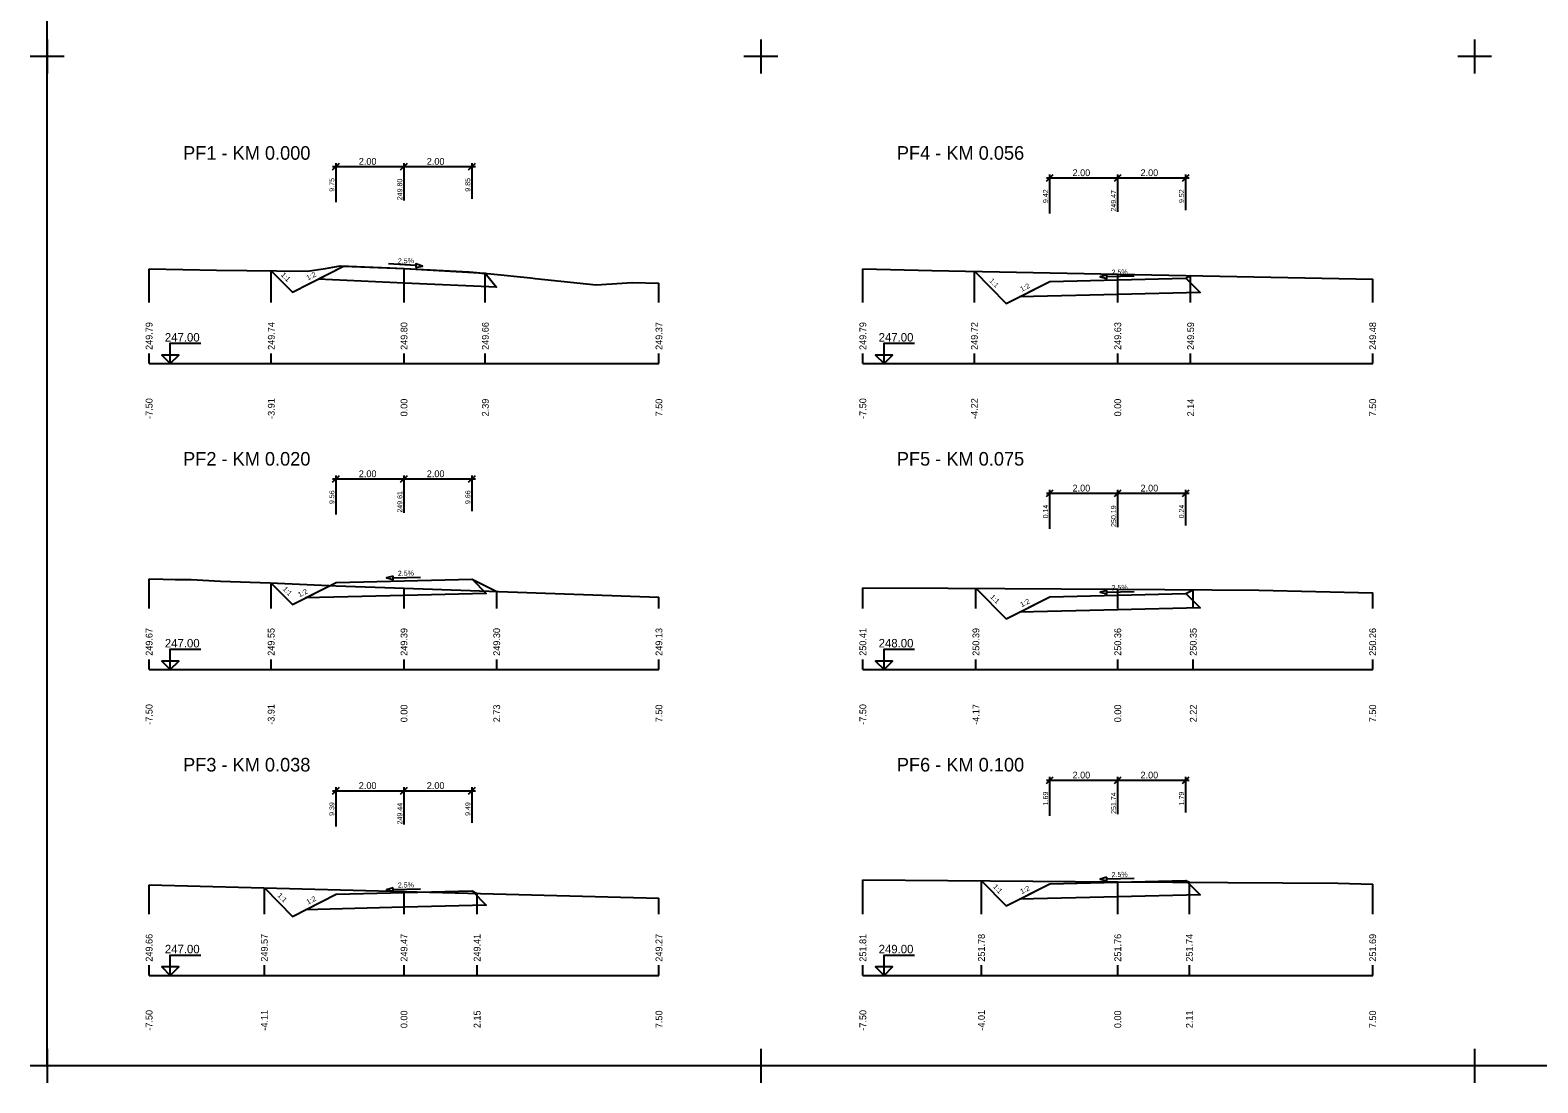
# Model space of a CAD drawing. Extents: x -5 to 1895, y -2 to 602.
# Drawn here: x -5 to 438.6, y -1.6 to 308.1 of the extents above; entities that cross this region are included whole.
import ezdxf

# ---------------------------------------------------------------- set-up
doc = ezdxf.new("R2010")
doc.units = 0
for name, color, linetype in [('KOTA', 7, 'Continuous'), ('KOTA_DELKY', 7, 'Continuous'), ('KOTA_DELKY_CONT', 7, 'Continuous'), ('NS_TELESO_VOZOVKY', 7, 'Continuous'), ('NS_V_PF', 7, 'Continuous'), ('REZY_PF_PUVODNI', 7, 'Continuous'), ('SESTAVY_REZU_PF', 7, 'Continuous'), ('SKLON', 7, 'Continuous'), ('SVK', 7, 'Continuous')]:
    doc.layers.add(name, color=color, linetype=linetype)

msp = doc.modelspace()

# ---------------------------------------------------------------- linework, layer by layer
for p, q in [((0, 305.39), (0, 295.39)), ((0, 305.39), (0, 295.39)), ((0, 305.39), (0, 295.39)), ((0, 305.39), (0, 295.39)), ((0, 305.39), (0, 295.39)), ((0, 305.39), (0, 295.39)), ((0, 305.39), (0, 295.39)), ((0, 305.39), (0, 295.39)), ((0, 305.39), (0, 295.39)), ((0, 305.39), (0, 295.39)), ((210, 305.39), (210, 295.39)), ((210, 305.39), (210, 295.39)), ((210, 305.39), (210, 295.39)), ((210, 305.39), (210, 295.39)), ((210, 305.39), (210, 295.39)), ((210, 305.39), (210, 295.39)), ((210, 305.39), (210, 295.39)), ((210, 305.39), (210, 295.39)), ((210, 305.39), (210, 295.39)), ((210, 305.39), (210, 295.39)), ((210, 305.39), (210, 295.39)), ((210, 305.39), (210, 295.39)), ((210, 305.39), (210, 295.39)), ((210, 305.39), (210, 295.39)), ((210, 305.39), (210, 295.39)), ((210, 305.39), (210, 295.39)), ((210, 305.39), (210, 295.39)), ((210, 305.39), (210, 295.39)), ((210, 305.39), (210, 295.39)), ((210, 305.39), (210, 295.39)), ((210, 305.39), (210, 295.39)), ((210, 305.39), (210, 295.39)), ((210, 305.39), (210, 295.39)), ((210, 305.39), (210, 295.39)), ((210, 305.39), (210, 295.39)), ((210, 305.39), (210, 295.39)), ((210, 305.39), (210, 295.39)), ((210, 305.39), (210, 295.39)), ((210, 305.39), (210, 295.39)), ((210, 305.39), (210, 295.39)), ((420, 305.39), (420, 295.39)), ((420, 305.39), (420, 295.39)), ((420, 305.39), (420, 295.39)), ((420, 305.39), (420, 295.39)), ((420, 305.39), (420, 295.39)), ((420, 305.39), (420, 295.39)), ((420, 305.39), (420, 295.39)), ((420, 305.39), (420, 295.39)), ((420, 305.39), (420, 295.39)), ((420, 305.39), (420, 295.39)), ((420, 305.39), (420, 295.39)), ((420, 305.39), (420, 295.39)), ((420, 305.39), (420, 295.39)), ((420, 305.39), (420, 295.39)), ((420, 305.39), (420, 295.39)), ((420, 305.39), (420, 295.39)), ((420, 305.39), (420, 295.39)), ((420, 305.39), (420, 295.39)), ((420, 305.39), (420, 295.39)), ((420, 305.39), (420, 295.39)), ((420, 305.39), (420, 295.39)), ((420, 305.39), (420, 295.39)), ((420, 305.39), (420, 295.39)), ((420, 305.39), (420, 295.39)), ((420, 305.39), (420, 295.39)), ((420, 305.39), (420, 295.39)), ((420, 305.39), (420, 295.39)), ((420, 305.39), (420, 295.39)), ((420, 305.39), (420, 295.39)), ((420, 305.39), (420, 295.39)), ((5, 300.39), (-5, 300.39)), ((5, 300.39), (-5, 300.39)), ((5, 300.39), (-5, 300.39)), ((5, 300.39), (-5, 300.39)), ((5, 300.39), (-5, 300.39)), ((5, 300.39), (-5, 300.39)), ((5, 300.39), (-5, 300.39)), ((5, 300.39), (-5, 300.39)), ((5, 300.39), (-5, 300.39)), ((5, 300.39), (-5, 300.39)), ((215, 300.39), (205, 300.39)), ((215, 300.39), (205, 300.39)), ((215, 300.39), (205, 300.39)), ((215, 300.39), (205, 300.39)), ((215, 300.39), (205, 300.39)), ((215, 300.39), (205, 300.39)), ((215, 300.39), (205, 300.39)), ((215, 300.39), (205, 300.39)), ((215, 300.39), (205, 300.39)), ((215, 300.39), (205, 300.39)), ((215, 300.39), (205, 300.39)), ((215, 300.39), (205, 300.39)), ((215, 300.39), (205, 300.39)), ((215, 300.39), (205, 300.39)), ((215, 300.39), (205, 300.39)), ((215, 300.39), (205, 300.39)), ((215, 300.39), (205, 300.39)), ((215, 300.39), (205, 300.39)), ((215, 300.39), (205, 300.39)), ((215, 300.39), (205, 300.39)), ((215, 300.39), (205, 300.39)), ((215, 300.39), (205, 300.39)), ((215, 300.39), (205, 300.39)), ((215, 300.39), (205, 300.39)), ((215, 300.39), (205, 300.39)), ((215, 300.39), (205, 300.39)), ((215, 300.39), (205, 300.39)), ((215, 300.39), (205, 300.39)), ((215, 300.39), (205, 300.39)), ((215, 300.39), (205, 300.39)), ((425, 300.39), (415, 300.39)), ((425, 300.39), (415, 300.39)), ((425, 300.39), (415, 300.39)), ((425, 300.39), (415, 300.39)), ((425, 300.39), (415, 300.39)), ((425, 300.39), (415, 300.39)), ((425, 300.39), (415, 300.39)), ((425, 300.39), (415, 300.39)), ((425, 300.39), (415, 300.39)), ((425, 300.39), (415, 300.39)), ((425, 300.39), (415, 300.39)), ((425, 300.39), (415, 300.39)), ((425, 300.39), (415, 300.39)), ((425, 300.39), (415, 300.39)), ((425, 300.39), (415, 300.39)), ((425, 300.39), (415, 300.39)), ((425, 300.39), (415, 300.39)), ((425, 300.39), (415, 300.39)), ((425, 300.39), (415, 300.39)), ((425, 300.39), (415, 300.39)), ((425, 300.39), (415, 300.39)), ((425, 300.39), (415, 300.39)), ((425, 300.39), (415, 300.39)), ((425, 300.39), (415, 300.39)), ((425, 300.39), (415, 300.39)), ((425, 300.39), (415, 300.39)), ((425, 300.39), (415, 300.39)), ((425, 300.39), (415, 300.39)), ((425, 300.39), (415, 300.39)), ((425, 300.39), (415, 300.39)), ((0, 8.39), (0, -1.61)), ((0, 8.39), (0, -1.61)), ((0, 8.39), (0, -1.61)), ((0, 8.39), (0, -1.61)), ((210, 8.39), (210, -1.61)), ((210, 8.39), (210, -1.61)), ((210, 8.39), (210, -1.61)), ((210, 8.39), (210, -1.61)), ((210, 8.39), (210, -1.61)), ((210, 8.39), (210, -1.61)), ((210, 8.39), (210, -1.61)), ((210, 8.39), (210, -1.61)), ((210, 8.39), (210, -1.61)), ((210, 8.39), (210, -1.61)), ((210, 8.39), (210, -1.61)), ((210, 8.39), (210, -1.61)), ((420, 8.39), (420, -1.61)), ((420, 8.39), (420, -1.61)), ((420, 8.39), (420, -1.61)), ((420, 8.39), (420, -1.61)), ((420, 8.39), (420, -1.61)), ((420, 8.39), (420, -1.61)), ((420, 8.39), (420, -1.61)), ((420, 8.39), (420, -1.61)), ((420, 8.39), (420, -1.61)), ((420, 8.39), (420, -1.61)), ((420, 8.39), (420, -1.61)), ((420, 8.39), (420, -1.61)), ((5, 3.39), (-5, 3.39)), ((5, 3.39), (-5, 3.39)), ((5, 3.39), (-5, 3.39)), ((5, 3.39), (-5, 3.39)), ((215, 3.39), (205, 3.39)), ((215, 3.39), (205, 3.39)), ((215, 3.39), (205, 3.39)), ((215, 3.39), (205, 3.39)), ((215, 3.39), (205, 3.39)), ((215, 3.39), (205, 3.39)), ((215, 3.39), (205, 3.39)), ((215, 3.39), (205, 3.39)), ((215, 3.39), (205, 3.39)), ((215, 3.39), (205, 3.39)), ((215, 3.39), (205, 3.39)), ((215, 3.39), (205, 3.39)), ((425, 3.39), (415, 3.39)), ((425, 3.39), (415, 3.39)), ((425, 3.39), (415, 3.39)), ((425, 3.39), (415, 3.39)), ((425, 3.39), (415, 3.39)), ((425, 3.39), (415, 3.39)), ((425, 3.39), (415, 3.39)), ((425, 3.39), (415, 3.39)), ((425, 3.39), (415, 3.39)), ((425, 3.39), (415, 3.39)), ((425, 3.39), (415, 3.39)), ((425, 3.39), (415, 3.39))]:
    msp.add_line(p, q)
msp.add_lwpolyline([(0, 597.39), (1890, 597.39), (1890, 3.39), (0, 3.39)], close=True)
at = {"layer": 'KOTA'}
for points in [[(36.22, 212.5), (33.72, 212.5), (36.22, 210), (36.22, 216), (45.22, 216)], [(246.22, 212.5), (243.72, 212.5), (246.22, 210), (246.22, 216), (255.22, 216)], [(36.22, 210), (38.72, 212.5), (36.22, 212.5)], [(246.22, 210), (248.72, 212.5), (246.22, 212.5)], [(36.22, 122.5), (33.72, 122.5), (36.22, 120), (36.22, 126), (45.22, 126)], [(246.22, 122.5), (243.72, 122.5), (246.22, 120), (246.22, 126), (255.22, 126)], [(36.22, 120), (38.72, 122.5), (36.22, 122.5)], [(246.22, 120), (248.72, 122.5), (246.22, 122.5)], [(36.22, 32.5), (33.72, 32.5), (36.22, 30), (36.22, 36), (45.22, 36)], [(246.22, 32.5), (243.72, 32.5), (246.22, 30), (246.22, 36), (255.22, 36)], [(36.22, 30), (38.72, 32.5), (36.22, 32.5)], [(246.22, 30), (248.72, 32.5), (246.22, 32.5)]]:
    msp.add_lwpolyline(points, dxfattribs=at)
at = {"layer": 'KOTA_DELKY'}
for points in [[(84, 267.01), (86, 269.01)], [(84, 268.01), (106, 268.01)], [(85, 257.51), (85, 269.01)], [(104, 267.01), (106, 269.01)], [(104, 267.01), (106, 269.01)], [(104, 268.01), (126, 268.01)], [(105, 258.01), (105, 269.01)], [(105, 258.01), (105, 269.01)], [(124, 267.01), (126, 269.01)], [(125, 258.51), (125, 269.01)], [(294, 263.68), (296, 265.68)], [(294, 264.68), (316, 264.68)], [(295, 254.18), (295, 265.68)], [(314, 263.68), (316, 265.68)], [(314, 263.68), (316, 265.68)], [(314, 264.68), (336, 264.68)], [(315, 254.68), (315, 265.68)], [(315, 254.68), (315, 265.68)], [(334, 263.68), (336, 265.68)], [(335, 255.18), (335, 265.68)], [(84, 175.1), (86, 177.1)], [(84, 176.1), (106, 176.1)], [(85, 165.6), (85, 177.1)], [(104, 175.1), (106, 177.1)], [(104, 175.1), (106, 177.1)], [(104, 176.1), (126, 176.1)], [(105, 166.1), (105, 177.1)], [(105, 166.1), (105, 177.1)], [(124, 175.1), (126, 177.1)], [(125, 166.6), (125, 177.1)], [(294, 170.88), (296, 172.88)], [(294, 171.88), (316, 171.88)], [(295, 161.38), (295, 172.88)], [(314, 170.88), (316, 172.88)], [(314, 170.88), (316, 172.88)], [(314, 171.88), (336, 171.88)], [(315, 161.88), (315, 172.88)], [(315, 161.88), (315, 172.88)], [(334, 170.88), (336, 172.88)], [(335, 162.38), (335, 172.88)], [(84, 83.36), (86, 85.36)], [(84, 84.36), (106, 84.36)], [(85, 73.86), (85, 85.36)], [(104, 83.36), (106, 85.36)], [(104, 83.36), (106, 85.36)], [(104, 84.36), (126, 84.36)], [(105, 74.36), (105, 85.36)], [(105, 74.36), (105, 85.36)], [(124, 83.36), (126, 85.36)], [(125, 74.86), (125, 85.36)], [(294, 86.45), (296, 88.45)], [(294, 87.45), (316, 87.45)], [(295, 76.95), (295, 88.45)], [(314, 86.45), (316, 88.45)], [(314, 86.45), (316, 88.45)], [(314, 87.45), (336, 87.45)], [(315, 77.45), (315, 88.45)], [(315, 77.45), (315, 88.45)], [(334, 86.45), (336, 88.45)], [(335, 77.95), (335, 88.45)]]:
    msp.add_lwpolyline(points, dxfattribs=at)
at = {"layer": 'NS_TELESO_VOZOVKY'}
for points in [[(105, 238.01), (128.89, 236.58), (128.89, 236.58), (132.21, 232.46), (105, 233.71), (79.7, 234.86), (87.2, 238.69), (87.2, 238.69), (105, 238.01)], [(315, 234.68), (335, 235.18), (335, 235.18), (339.2, 230.98), (315, 230.38), (286.05, 229.65), (295, 234.18), (295, 234.18), (315, 234.68)], [(105, 146.1), (125, 146.6), (125, 146.6), (129.2, 142.4), (105, 141.8), (76.05, 141.08), (85, 145.6), (85, 145.6), (105, 146.1)], [(315, 141.88), (335, 142.38), (335, 142.38), (339.2, 138.19), (315, 137.58), (286.05, 136.86), (295, 141.38), (295, 141.38), (315, 141.88)], [(315, 57.45), (335, 57.95), (335, 57.95), (339.2, 53.75), (315, 53.15), (286.05, 52.43), (295, 56.95), (295, 56.95), (315, 57.45)], [(105, 54.36), (125, 54.86), (125, 54.86), (129.2, 50.66), (105, 50.06), (76.05, 49.34), (85, 53.86), (85, 53.86), (105, 54.36)]]:
    msp.add_lwpolyline(points, dxfattribs=at)
at = {"layer": 'NS_V_PF'}
for points in [[(65.94, 237.35), (72.19, 231.04), (87.2, 238.69), (87.2, 238.69), (105, 238.01), (124.21, 236.97), (124.21, 236.97), (128.92, 236.55)], [(272.82, 237.17), (282.19, 227.7), (295, 234.18), (295, 234.18), (315, 234.68), (335, 235.18), (335, 235.18), (336.43, 235.89)], [(65.91, 145.46), (72.19, 139.12), (85, 145.6), (85, 145.6), (105, 146.1), (125, 146.6), (125, 146.6), (132.27, 142.96)], [(273.26, 143.93), (282.19, 134.9), (295, 141.38), (295, 141.38), (315, 141.88), (335, 142.38), (335, 142.38), (337.21, 143.49)], [(274.89, 57.84), (282.19, 50.47), (295, 56.95), (295, 56.95), (315, 57.45), (335, 57.95), (335, 57.95), (336.06, 57.42)], [(63.91, 55.75), (72.19, 47.38), (85, 53.86), (85, 53.86), (105, 54.36), (125, 54.86), (125, 54.86), (126.51, 54.11)]]:
    msp.add_lwpolyline(points, dxfattribs=at)
at = {"layer": 'REZY_PF_PUVODNI'}
for points in [[(30, 237.88), (49.84, 237.52), (76.52, 237.24), (81.87, 237.99), (86.21, 238.74), (100.87, 238.24), (105, 238.01), (124.21, 236.97), (130.52, 236.41), (142.2, 235.26), (143.63, 235.01), (161.57, 233.24), (172.23, 233.9), (180, 233.67)], [(240, 237.92), (260.27, 237.42), (315, 236.32), (390, 234.82)], [(30, 146.68), (34.16, 146.61), (37.66, 146.53), (42.36, 146.45), (50.98, 146.04), (65.65, 145.48), (85.02, 144.62), (105, 143.92), (180, 141.28)], [(240, 144.07), (265.09, 143.99), (315, 143.64), (356.49, 143.35), (390, 142.59)], [(240, 58.09), (315, 57.57), (379.76, 57.12), (390, 56.89)], [(30, 56.64), (105, 54.67), (180, 52.7)]]:
    msp.add_lwpolyline(points, dxfattribs=at)
at = {"layer": 'SESTAVY_REZU_PF'}
for points in [[(30, 210), (180, 210)], [(240, 210), (390, 210)], [(30, 120), (180, 120)], [(240, 120), (390, 120)], [(30, 30), (180, 30)], [(240, 30), (390, 30)]]:
    msp.add_lwpolyline(points, dxfattribs=at)
at = {"layer": 'SKLON'}
for points in [[(108.47, 238.84), (100.48, 239.33)], [(108.44, 238.34), (110.46, 238.72), (108.5, 239.34), (108.44, 238.34)], [(311.79, 236.1), (309.8, 235.55), (311.81, 235.1), (311.79, 236.1)], [(311.8, 235.6), (319.8, 235.8)], [(101.79, 147.52), (99.8, 146.97), (101.81, 146.52), (101.79, 147.52)], [(101.8, 147.02), (109.8, 147.22)], [(311.79, 143.3), (309.8, 142.75), (311.81, 142.3), (311.79, 143.3)], [(311.8, 142.8), (319.8, 143)], [(311.79, 58.87), (309.8, 58.32), (311.81, 57.87), (311.79, 58.87)], [(311.8, 58.37), (319.8, 58.57)], [(101.79, 55.78), (99.8, 55.23), (101.81, 54.78), (101.79, 55.78)], [(101.8, 55.28), (109.8, 55.48)]]:
    msp.add_lwpolyline(points, dxfattribs=at)
at = {"layer": 'SVK'}
for points in [[(30, 228), (30, 237.88)], [(65.94, 228), (65.94, 237.35)], [(105, 228), (105, 238.01)], [(128.92, 228), (128.92, 236.55)], [(240, 228), (240, 237.92)], [(272.82, 228), (272.82, 237.17)], [(315, 228), (315, 236.32)], [(336.43, 228), (336.43, 235.89)], [(180, 228), (180, 233.67)], [(390, 228), (390, 234.82)], [(30, 210), (30, 213)], [(65.94, 210), (65.94, 213)], [(105, 210), (105, 213)], [(128.92, 210), (128.92, 213)], [(180, 210), (180, 213)], [(240, 210), (240, 213)], [(272.82, 210), (272.82, 213)], [(315, 210), (315, 213)], [(336.43, 210), (336.43, 213)], [(390, 210), (390, 213)], [(30, 138), (30, 146.68)], [(65.91, 138), (65.91, 145.46)], [(105, 138), (105, 143.92)], [(132.27, 138), (132.27, 142.96)], [(240, 138), (240, 144.07)], [(273.26, 138), (273.26, 143.93)], [(315, 138), (315, 143.64)], [(337.21, 138), (337.21, 143.49)], [(390, 138), (390, 142.59)], [(180, 138), (180, 141.28)], [(30, 120), (30, 123)], [(65.91, 120), (65.91, 123)], [(105, 120), (105, 123)], [(132.27, 120), (132.27, 123)], [(180, 120), (180, 123)], [(240, 120), (240, 123)], [(273.26, 120), (273.26, 123)], [(315, 120), (315, 123)], [(337.21, 120), (337.21, 123)], [(390, 120), (390, 123)], [(240, 48), (240, 58.09)], [(274.89, 48), (274.89, 57.84)], [(30, 48), (30, 56.64)], [(63.91, 48), (63.91, 55.75)], [(105, 48), (105, 54.67)], [(126.51, 48), (126.51, 54.11)], [(315, 48), (315, 57.57)], [(336.06, 48), (336.06, 57.42)], [(390, 48), (390, 56.89)], [(180, 48), (180, 52.7)], [(30, 30), (30, 33)], [(63.91, 30), (63.91, 33)], [(105, 30), (105, 33)], [(126.51, 30), (126.51, 33)], [(180, 30), (180, 33)], [(240, 30), (240, 33)], [(274.89, 30), (274.89, 33)], [(315, 30), (315, 33)], [(336.06, 30), (336.06, 33)], [(390, 30), (390, 33)]]:
    msp.add_lwpolyline(points, dxfattribs=at)

# ---------------------------------------------------------------- texts
at = {"layer": 'KOTA'}
for s, p in [('247.00', (34.64, 216.5)), ('247.00', (244.64, 216.5)), ('247.00', (34.64, 126.5)), ('248.00', (244.64, 126.5)), ('247.00', (34.64, 36.5)), ('249.00', (244.64, 36.5))]:
    msp.add_text(s, height=2.5, dxfattribs=at).set_placement(p)
at = {"layer": 'KOTA_DELKY'}
for p in [(91.69, 268.51), (111.69, 268.51), (301.69, 265.18), (321.69, 265.18), (91.69, 176.6), (111.69, 176.6), (301.69, 172.38), (321.69, 172.38), (301.69, 87.95), (321.69, 87.95), (91.69, 84.86), (111.69, 84.86)]:
    msp.add_text('2.00', height=2, dxfattribs=at).set_placement(p)
at = {"layer": 'KOTA_DELKY_CONT'}
for s, p in [('9.75', (84.5, 260.6)), ('249.80', (104.5, 258.09)), ('9.85', (124.5, 260.6)), ('9.42', (294.5, 257.26)), ('249.47', (314.5, 254.75)), ('9.52', (334.5, 257.26)), ('9.56', (84.5, 168.69)), ('249.61', (104.5, 166.18)), ('9.66', (124.5, 168.69)), ('0.14', (294.5, 164.47)), ('250.19', (314.5, 161.96)), ('0.24', (334.5, 164.47)), ('9.39', (84.5, 76.95)), ('249.44', (104.5, 74.44)), ('9.49', (124.5, 76.95)), ('1.69', (294.5, 80.04)), ('251.74', (314.5, 77.53)), ('1.79', (334.5, 80.04))]:
    msp.add_text(s, height=1.5, rotation=90, dxfattribs=at).set_placement(p)
at = {"layer": 'SESTAVY_REZU_PF'}
for s, p in [('PF1 - KM 0.000', (40, 270)), ('PF4 - KM 0.056', (250, 270)), ('PF2 - KM 0.020', (40, 180)), ('PF5 - KM 0.075', (250, 180)), ('PF3 - KM 0.038', (40, 90)), ('PF6 - KM 0.100', (250, 90))]:
    msp.add_text(s, height=4, dxfattribs=at).set_placement(p)
at = {"layer": 'SKLON'}
for s, rotation, p in [('2.5%', 1.4321, (103.2, 239.47)), ('1:1', 314.7121, (68.67, 236.02)), ('1:2', 26.8233, (76.74, 234.46)), ('2.5%', 1.4321, (313.2, 236.13)), ('1:1', 314.7121, (277.11, 234.26)), ('1:2', 26.8233, (286.74, 231.12)), ('2.5%', 1.4321, (103.2, 147.55)), ('1:1', 314.7121, (69.17, 143.59)), ('1:2', 26.8233, (74.25, 141.21)), ('1:1', 314.7121, (277.33, 141.24)), ('2.5%', 1.4321, (313.2, 143.34)), ('1:2', 26.8233, (286.74, 138.32)), ('2.5%', 1.4321, (313.2, 58.9)), ('1:1', 314.7121, (67.65, 53.39)), ('1:2', 26.8233, (76.74, 50.8)), ('2.5%', 1.4321, (103.2, 55.81)), ('1:1', 314.7121, (278.14, 55.98)), ('1:2', 26.8233, (286.74, 53.89))]:
    msp.add_text(s, height=1.5, rotation=rotation, dxfattribs=at).set_placement(p)
at = {"layer": 'SVK'}
for s, p in [(' 249.79', (31, 213.3)), (' 249.74', (66.94, 213.3)), (' 249.80', (106, 213.3)), (' 249.66', (129.92, 213.3)), (' 249.37', (181, 213.3)), (' 249.79', (241, 213.3)), (' 249.72', (273.82, 213.3)), (' 249.63', (316, 213.3)), (' 249.59', (337.43, 213.3)), (' 249.48', (391, 213.3)), (' -7.50', (31, 193)), (' -3.91', (66.94, 193)), (' -7.50', (241, 193)), (' -4.22', (273.82, 193)), ('  0.00', (106, 193)), ('  2.39', (129.92, 193)), ('  7.50', (181, 193)), ('  0.00', (316, 193)), ('  2.14', (337.43, 193)), ('  7.50', (391, 193)), (' 249.67', (31, 123.3)), (' 249.55', (66.91, 123.3)), (' 249.39', (106, 123.3)), (' 249.30', (133.27, 123.3)), (' 249.13', (181, 123.3)), (' 250.41', (241, 123.3)), (' 250.39', (274.26, 123.3)), (' 250.36', (316, 123.3)), (' 250.35', (338.21, 123.3)), (' 250.26', (391, 123.3)), (' -7.50', (31, 103)), (' -3.91', (66.91, 103)), ('  0.00', (106, 103)), ('  2.73', (133.27, 103)), ('  7.50', (181, 103)), (' -7.50', (241, 103)), (' -4.17', (274.26, 103)), ('  0.00', (316, 103)), ('  2.22', (338.21, 103)), ('  7.50', (391, 103)), (' 249.66', (31, 33.3)), (' 249.57', (64.91, 33.3)), (' 249.47', (106, 33.3)), (' 249.41', (127.51, 33.3)), (' 249.27', (181, 33.3)), (' 251.81', (241, 33.3)), (' 251.78', (275.89, 33.3)), (' 251.76', (316, 33.3)), (' 251.74', (337.06, 33.3)), (' 251.69', (391, 33.3)), (' -7.50', (31, 13)), (' -4.11', (64.91, 13)), ('  0.00', (106, 13)), ('  2.15', (127.51, 13)), ('  7.50', (181, 13)), (' -7.50', (241, 13)), (' -4.01', (275.89, 13)), ('  0.00', (316, 13)), ('  2.11', (337.06, 13)), ('  7.50', (391, 13))]:
    msp.add_text(s, height=2, rotation=90, dxfattribs=at).set_placement(p)

doc.saveas('drawing.dxf')
